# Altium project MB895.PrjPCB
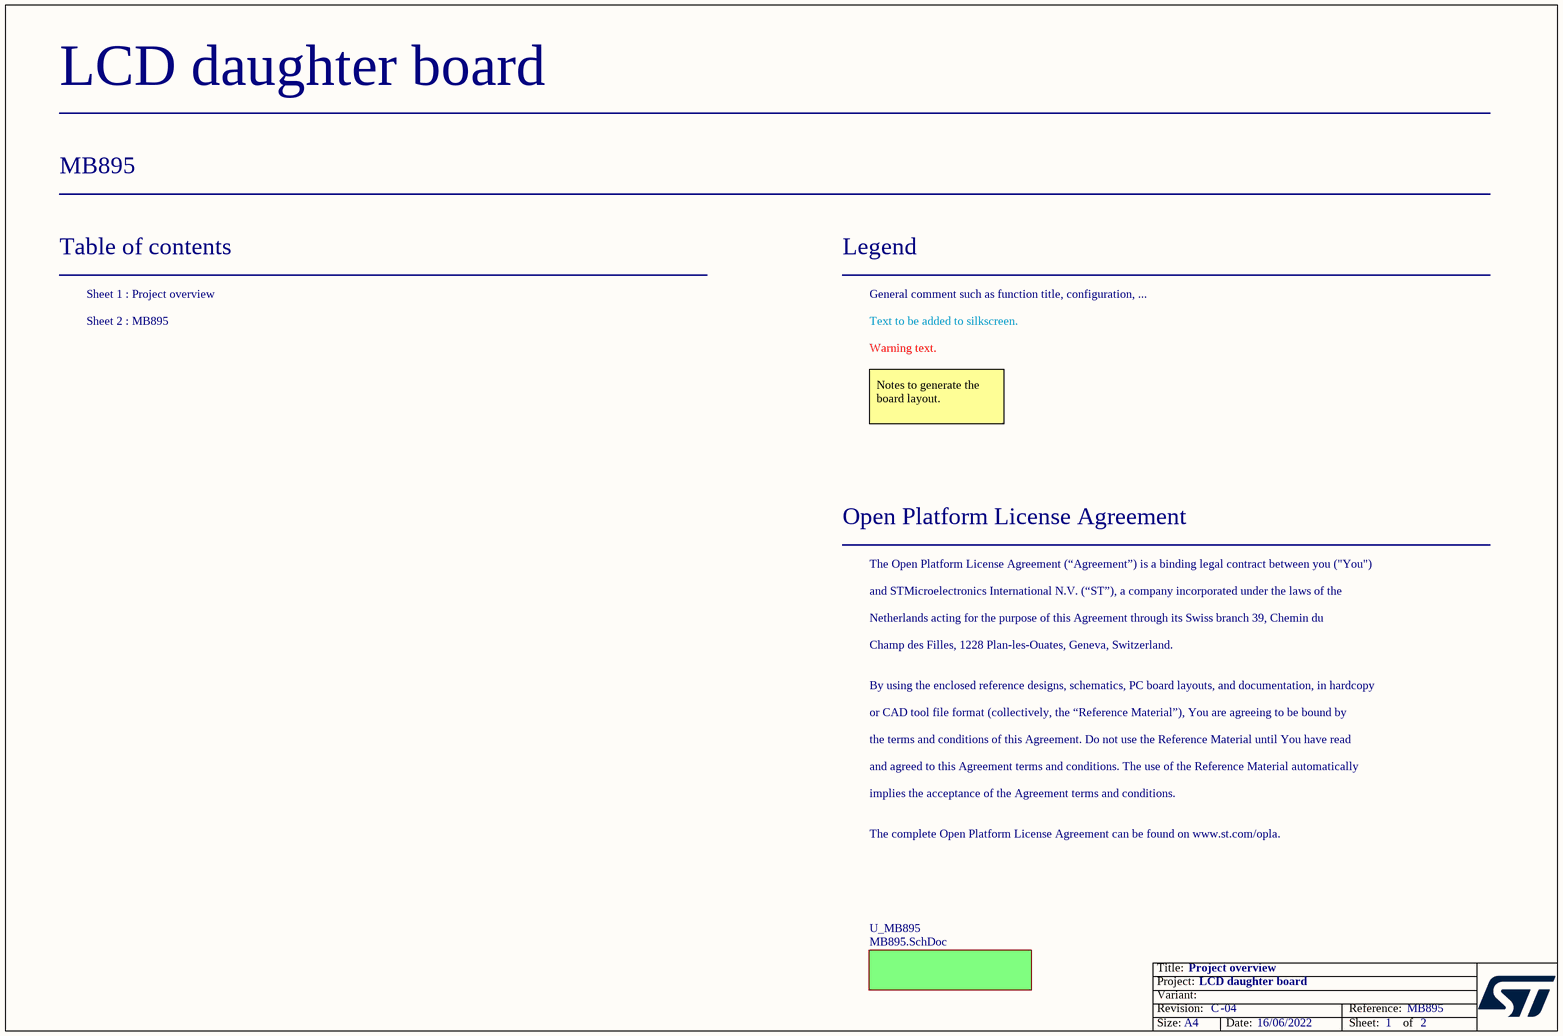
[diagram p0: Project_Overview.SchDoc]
Board_Assembly_Revision: 04; Board_Document_Date: 16/06/2022; Board_Name: LCD daughter board; Board_PCB_Revision: C; Board_Reference: MB895
2 sheets, 41 parts. Net scope: global (net labels, ports and power ports of the same name join across sheets).
Board file: MB895.PCBDOC
Sheets:
  Project_Overview.SchDoc
    U_MB895 = MB895.SchDoc

## Sheet Project_Overview.SchDoc: Project overview
size A4; Date: Not used; ApprovedBy: Not used; CheckedBy: Not used; Author: Not used; CompanyName: STMicroelectronics; DrawnBy: Not used; Engineer: Not used; Organization: Not used; Address1: Not used; Address2: Not used; Address3: Not used; Address4: Not used; DocumentNumber: Not used; Revision: Not used; SheetNumber: 1; SheetTotal: 2

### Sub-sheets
U_MB895 = MB895.SchDoc: no entries

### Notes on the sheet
- LCD daughter board
- MB895
- Table of contents
- Sheet 1 : Project overview
- Legend
- General comment such as function title, configuration, ...
- Sheet 2 : MB895
- Text to be added to silkscreen.
- Warning text.
- Notes to generate the board layout.
- Open Platform License Agreement
- The Open Platform License Agreement (“Agreement”) is a binding legal contract between you ("You")
- and STMicroelectronics International N.V. (“ST”), a company incorporated under the laws of the
- Netherlands acting for the purpose of this Agreement through its Swiss branch 39, Chemin du
- Champ des Filles, 1228 Plan-les-Ouates, Geneva, Switzerland.
- By using the enclosed reference designs, schematics, PC board layouts, and documentation, in hardcopy
- or CAD tool file format (collectively, the “Reference Material”), You are agreeing to be bound by
- the terms and conditions of this Agreement. Do not use the Reference Material until You have read
- and agreed to this Agreement terms and conditions. The use of the Reference Material automatically
- implies the acceptance of the Agreement terms and conditions.
- The complete Open Platform License Agreement can be found on www.st.com/opla.

## Sheet MB895.SchDoc: 2.4 inch LCD board support either SPI or 16-bit parallel
size A4; Date: Not used; ApprovedBy: Not used; CheckedBy: Not used; Author: Not used; CompanyName: STMicroelectronics; DrawnBy: Not used; Engineer: Not used; Organization: Not used; Address1: Not used; Address2: Not used; Address3: Not used; Address4: Not used; DocumentNumber: Not used; Revision: Not used; SheetNumber: 2; SheetTotal: 2
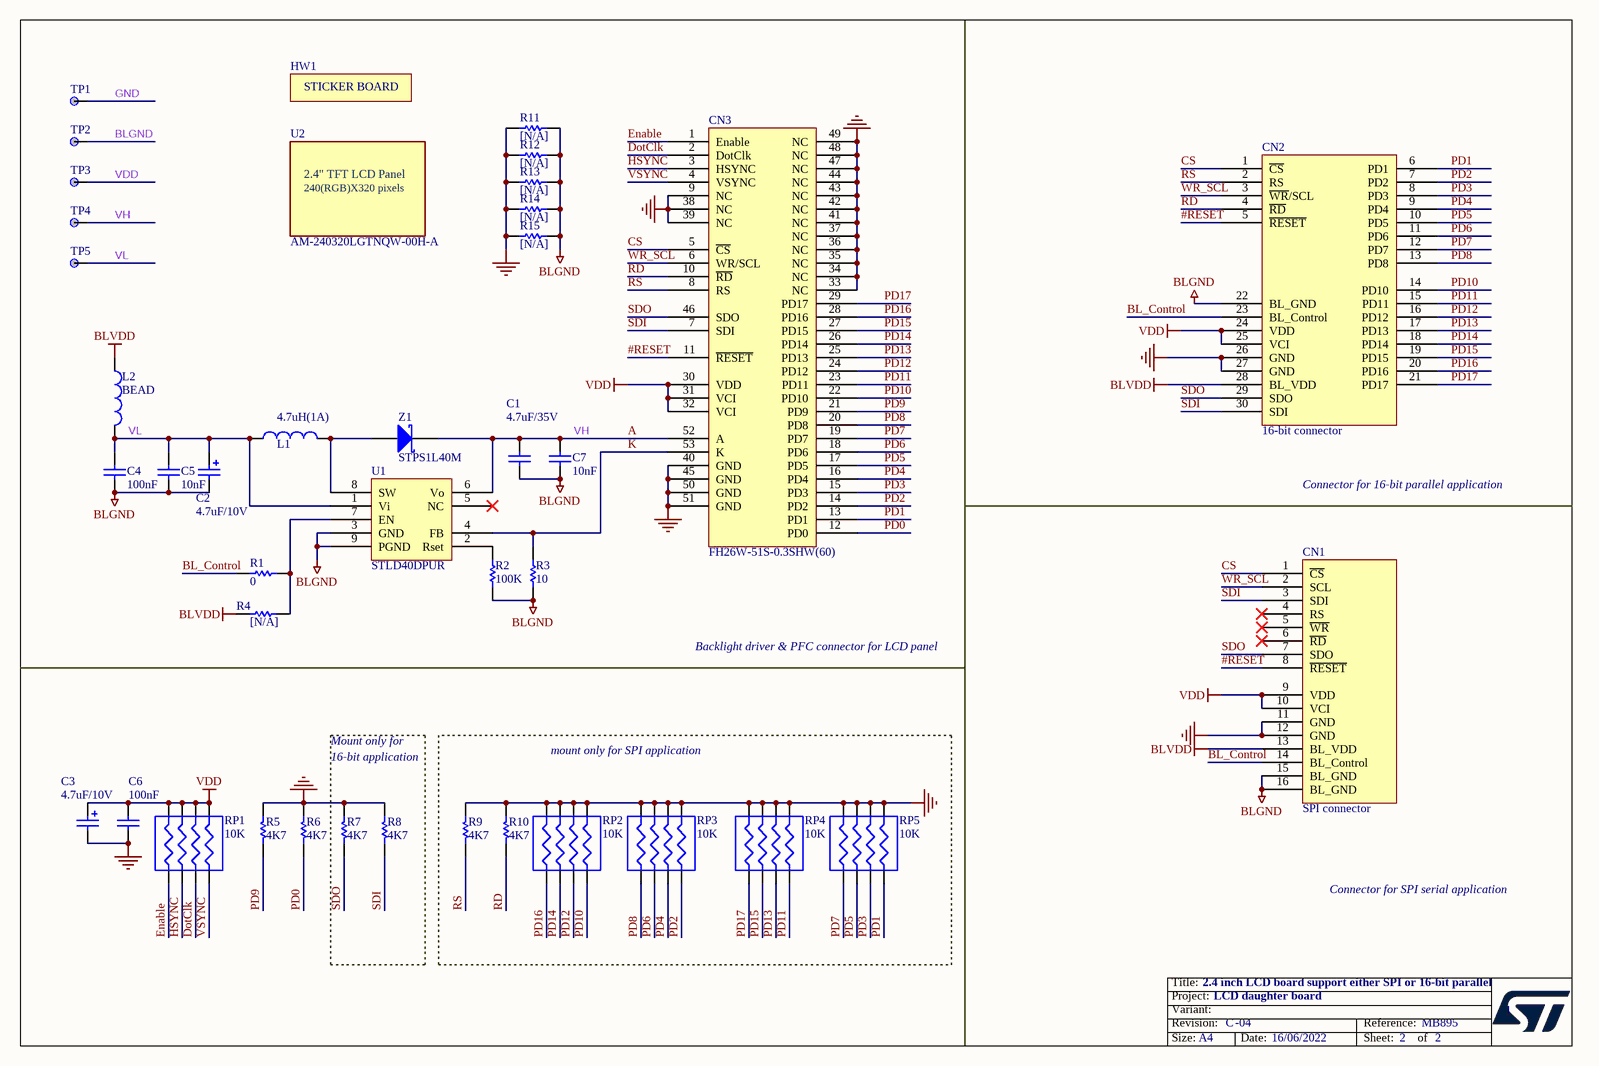
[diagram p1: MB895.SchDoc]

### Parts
C1  4.7uF/35V  [3225C]
C2  4.7uF/10V  [3225C]
C3  4.7uF/10V  [1206C]
C4  100nF  [0402C]
C5  10nF  [0402C]
C6  100nF  [0402C]
C7  10nF  [0603C]
CN1  SPI connector  [AM240320A]
CN2  16-bit connector  [AM240*320B]
CN3  FH26W-51S-0.3SHW(60)
HW1  STICKER_BOARD  (value not drawn)  (no BOM)
L1  4.7uH(1A)  [3225L]
L2  BEAD  [0603L]
R1  0  [0603R]
R2  100K  [0603R]
R3  10  [0603R]
R4  [N/A]  [0603R]
R5  4K7  [0402R]
R6  4K7  [0402R]
R7  4K7  [0402R]
R8  4K7  [0402R]
R9  4K7  [0402R]
R10  4K7  [0402R]
R11  [N/A]  [0603R]
R12  [N/A]  [0603R]
R13  [N/A]  [0603R]
R14  [N/A]  [0603R]
R15  [N/A]  [0603R]
RP1  10K  [RES-4B]
RP2  10K  [RES-4B]
RP3  10K  [RES-4B]
RP4  10K  [RES-4B]
RP5  10K  [RES-4B]
TP1  (no value)  [TP]
TP2  (no value)  [TP]
TP3  (no value)  [TP]
TP4  (no value)  [TP]
TP5  (no value)  [TP]
U1  STLD40DPUR  [QFNT8]
U2  AM-240320LGTNQW-00H-A
Z1  STPS1L40M  [DO216AA]

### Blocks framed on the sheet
mount only for SPI application: R9 R10 RP2-RP5

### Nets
BLGND: C1.2 C2.2 C4.1 C5.1 C7.1 CN1.15(BL_GND) CN1.16(BL_GND) CN2.22(BL_GND) R2.2 R3.1 R11.1 R12.1 R13.1 R14.1 R15.1 TP2.1 U1.3(GND) U1.9(PGND)
BLVDD: CN1.13(BL_VDD) CN2.28(BL_VDD) L2.1 R4.2
GND: C3.2 C6.1 CN1.11(GND) CN1.12(GND) CN2.26(GND) CN2.27(GND) CN3.9(NC) CN3.33(NC) CN3.34(NC) CN3.35(NC) CN3.36(NC) CN3.37(NC) CN3.38(NC) CN3.39(NC) CN3.40(GND) CN3.41(NC) CN3.42(NC) CN3.43(NC) CN3.44(NC) CN3.45(GND) CN3.47(NC) CN3.48(NC) CN3.49(NC) CN3.50(GND) CN3.51(GND) R5.1 R6.1 R7.1 R8.1 R9.1 R10.1 R11.2 R12.2 R13.2 R14.2 R15.2 RP2.2(R1) RP2.4(R3) RP2.6(R2) RP2.8(R0) RP3.2(R1) RP3.4(R3) RP3.6(R2) RP3.8(R0) RP4.2(R1) RP4.4(R3) RP4.6(R2) RP4.8(R0) RP5.2(R1) RP5.4(R3) RP5.6(R2) RP5.8(R0) TP1.1
VDD: C3.1 C6.2 CN1.9(VDD) CN1.10(VCI) CN2.24(VDD) CN2.25(VCI) CN3.30(VDD) CN3.31(VCI) CN3.32(VCI) RP1.2(R1) RP1.4(R3) RP1.6(R2) RP1.8(R0) TP3.1
#RESET: CN1.8(~{RESET}) CN2.5(~{RESET}) CN3.11(~{RESET})
A: C1.1 C7.2 CN3.52(A) TP4.1 U1.6(Vo) Z1.2(K)  [also labelled VH]
BL_Control: CN1.14(BL_Control) CN2.23(BL_Control) R1.2
CS: CN1.1(~{CS}) CN2.1(~{CS}) CN3.5(~{CS})
DotClk: CN3.2(DotClk) RP1.5(R3)
Enable: CN3.1(Enable) RP1.1(R0)
HSYNC: CN3.3(HSYNC) RP1.3(R2)
K: CN3.53(K) R3.2 U1.4(FB)
PD0: CN3.12(PD0) R6.2
PD1: CN2.6(PD1) CN3.13(PD1) RP5.7(R1)
PD2: CN2.7(PD2) CN3.14(PD2) RP3.7(R1)
PD3: CN2.8(PD3) CN3.15(PD3) RP5.5(R3)
PD4: CN2.9(PD4) CN3.16(PD4) RP3.5(R3)
PD5: CN2.10(PD5) CN3.17(PD5) RP5.3(R2)
PD6: CN2.11(PD6) CN3.18(PD6) RP3.3(R2)
PD7: CN2.12(PD7) CN3.19(PD7) RP5.1(R0)
PD8: CN2.13(PD8) CN3.20(PD8) RP3.1(R0)
PD9: CN3.21(PD9) R5.2
PD10: CN2.14(PD10) CN3.22(PD10) RP2.7(R1)
PD11: CN2.15(PD11) CN3.23(PD11) RP4.7(R1)
PD12: CN2.16(PD12) CN3.24(PD12) RP2.5(R3)
PD13: CN2.17(PD13) CN3.25(PD13) RP4.5(R3)
PD14: CN2.18(PD14) CN3.26(PD14) RP2.3(R2)
PD15: CN2.19(PD15) CN3.27(PD15) RP4.3(R2)
PD16: CN2.20(PD16) CN3.28(PD16) RP2.1(R0)
PD17: CN2.21(PD17) CN3.29(PD17) RP4.1(R0)
RD: CN2.4(~{RD}) CN3.10(~{RD}) R10.2
RS: CN2.2(RS) CN3.8(RS) R9.2
SDI: CN1.3(SDI) CN2.30(SDI) CN3.7(SDI) R8.2
SDO: CN1.7(SDO) CN2.29(SDO) CN3.46(SDO) R7.2
VL: C2.1 C4.2 C5.2 L1.1 L2.2 TP5.1 U1.1(Vi)
VSYNC: CN3.4(VSYNC) RP1.7(R1)
WR_SCL: CN1.2(SCL) CN2.3(~{WR}/SCL) CN3.6(WR/SCL)
NetL1_2: L1.2 U1.8(SW) Z1.1(A)
NetR1_1: R1.1 R4.1 U1.7(EN)
NetR2_1: R2.1 U1.2(Rset)

Not connected (* = marked no-connect by the designer): CN1 4(RS)* 5(~{WR})* 6(~{RD})*; U1 5(NC)*

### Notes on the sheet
- Connector for 16-bit parallel application
- Backlight driver & PFC connector for LCD panel
- Mount only for
- 16-bit application
- Connector for SPI serial application
- 1

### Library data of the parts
C1 C4-C7 = CAP: Capacitor; Value: 100pF
C2 C3 = Cap Pol1: Polarized Capacitor (Radial); Value: 100pF
CN1 CN2 = ColorLCD_module
CN3 = AM240320LTNQW00H
L1 L2 = Inductor: Value: 100uH
R1-R10 = Res1: Resistor; Value: 1K
R11-R15 = Res1: Resistor
RP1-RP5 = RES4B
TP1-TP5 = TP
U1 = STLD40DPMR
Z1 = D Schottky: Schottky Diode; Code - JEDEC: DO-214-AA

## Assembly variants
Parallel: not fitted CN1 R4 R9 R10 R11 R12 R13 R14 R15 RP2 RP3 RP4 RP5 TP1 TP2 TP3 TP4 TP5; alternate parts U2 -> AM-240320LGTNQW-01H-B
Serial: not fitted CN2 R4 R7 R8 R11 R12 R13 R14 R15 TP1 TP2 TP3 TP4 TP5; alternate parts U2 -> AM-240320LGTNQW-00H-A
